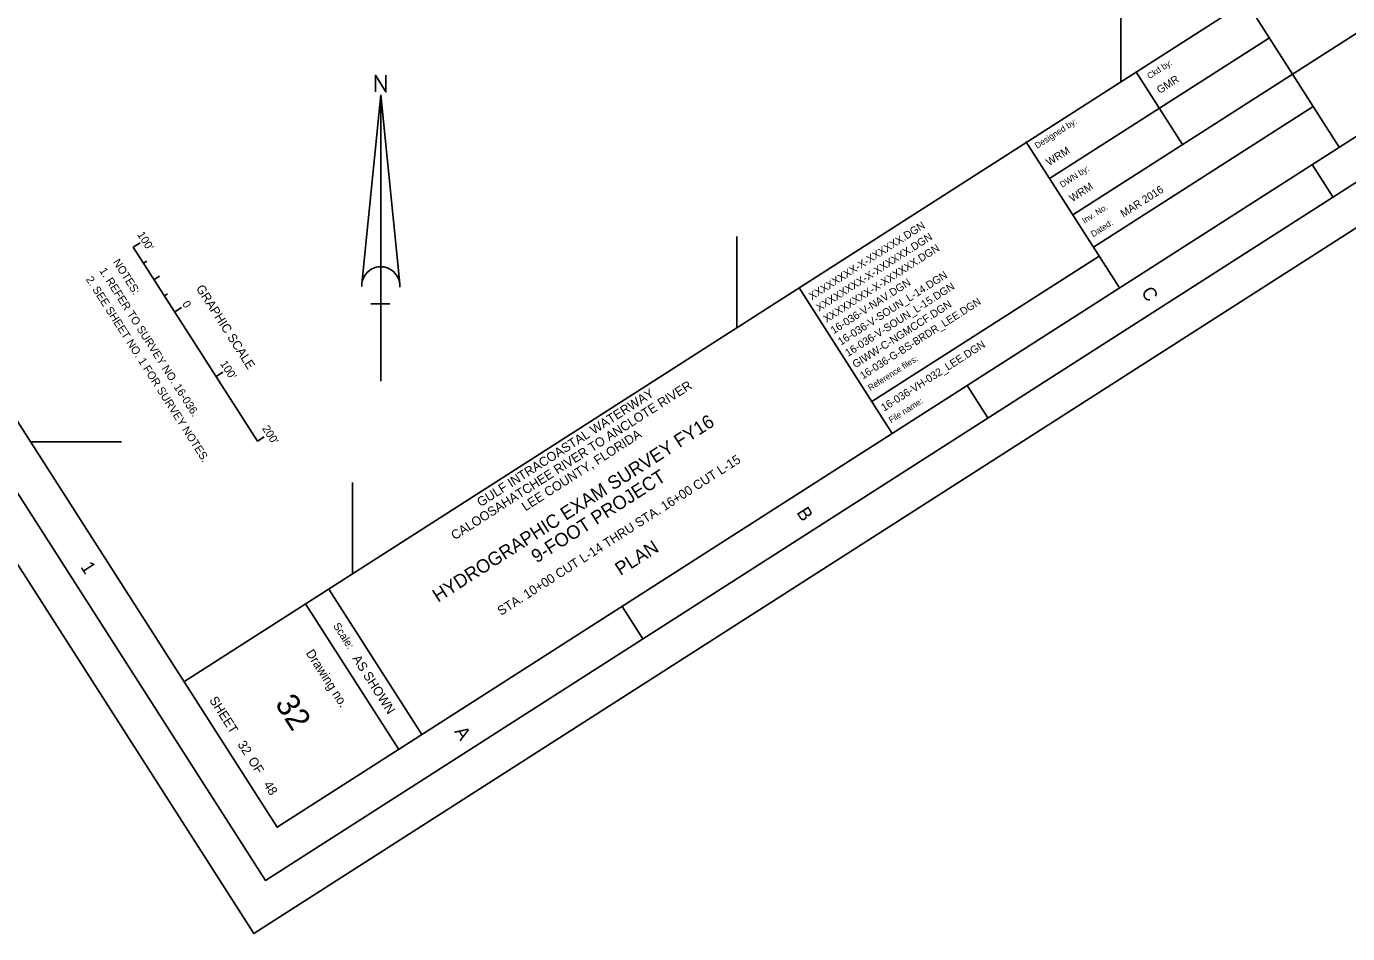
# Model space of a CAD drawing. Extents: x 584499 to 589735, y 833860 to 839399.
# Drawn here: x 586575 to 588295, y 833860 to 835040 of the extents above; entities that cross this region are included whole.
import ezdxf

# ---------------------------------------------------------------- set-up
doc = ezdxf.new("R2010")
doc.units = 0
for name, color, linetype in [('G-ANNO-NPLT', 7, 'Continuous'), ('G-ANNO-TEXT-DRWG', 7, 'Continuous'), ('G-ANNO-TEXT-PROJ', 7, 'Continuous'), ('G-ANNO-TEXT-TTLB', 7, 'Continuous'), ('G-ANNO-TTLB', 7, 'Continuous'), ('V-ANNO-NOTE', 7, 'Continuous'), ('V-ANNO-SYMB', 7, 'Continuous'), ('V-TOPO-COOR-STAT', 7, 'Continuous')]:
    doc.layers.add(name, color=color, linetype=linetype)

msp = doc.modelspace()

# ---------------------------------------------------------------- linework, layer by layer
at = {"layer": 'G-ANNO-NPLT'}
msp.add_lwpolyline([(587362.9, 839398.7), (589735, 835692.9), (586871.4, 833859.9), (584499.3, 837565.7)], close=True, dxfattribs=at)
msp.add_lwpolyline([(586913.6, 833886.8), (586871.5, 833859.8), (586844.5, 833901.9)], dxfattribs=at)
at = {"layer": 'G-ANNO-TTLB'}
for p, q in [((589475.5, 835912.7), (586780.4, 834187.6)), ((587937.4, 834795.4), (588661.7, 835258.2)), ((588162.8, 835073.4), (588284.5, 834883.2)), ((587907.3, 834842.5), (588193.5, 835025.4)), ((588019.7, 834981.8), (588080.5, 834886.8)), ((588250.5, 834936.2), (587964.5, 834753.1)), ((587876.5, 834890.6), (587998.4, 834700.1)), ((588276.1, 834818.5), (588249.2, 834860.6)), ((587971.8, 834741.6), (587675.9, 834552.2)), ((587581.2, 834700.2), (587702.5, 834510.6)), ((587827, 834531), (587800, 834573.1)), ((586968.8, 834308.2), (587090.2, 834118.7)), ((586938.8, 834289), (587060.1, 834099.5)), ((587377.8, 834243.5), (587350.9, 834285.6))]:
    msp.add_line(p, q, dxfattribs=at)
for points in [[(584568.4, 837550.6), (586886.5, 833929), (589665.9, 835708.1), (587347.7, 839329.7)], [(589596.8, 835723.2), (587373, 839197.4), (584677.9, 837472.3), (586901.7, 833998.1)]]:
    msp.add_lwpolyline(points, close=True, dxfattribs=at)
at = {"layer": 'V-ANNO-NOTE'}
for p, q in [((586714.4, 834753.1), (586723.2, 834758.8)), ((586714.4, 834753.1), (586876.2, 834500.5)), ((586727.9, 834732.1), (586731.9, 834734.7)), ((586741.4, 834711), (586748.6, 834715.6)), ((586754.9, 834690), (586758.9, 834692.6)), ((586768.3, 834668.9), (586777.1, 834674.5)), ((586768.3, 834668.9), (586777.1, 834674.5)), ((586768.3, 834668.9), (586772.5, 834671.6)), ((586822.2, 834584.7), (586831, 834590.3)), ((586876.2, 834500.5), (586885, 834506.1))]:
    msp.add_line(p, q, dxfattribs=at)
at = {"layer": 'V-ANNO-SYMB'}
for p, q in [((587011.9, 834705.4), (587036.6, 834951.2)), ((587036.6, 834578.8), (587036.6, 834951.2)), ((587061.3, 834705.4), (587036.6, 834951.2)), ((587048.4, 834679.4), (587023.6, 834679.4))]:
    msp.add_line(p, q, dxfattribs=at)
msp.add_lwpolyline([(587029.8, 834955.1), (587029.8, 834976.9), (587043.3, 834955.1), (587043.3, 834976.9)], dxfattribs=at)
msp.add_arc((587036.6, 834702.9), 24.8, 355.2984, 182.0673, dxfattribs=at)
at = {"layer": 'V-TOPO-COOR-STAT'}
for p, q in [((588000, 834968.3), (588000, 835087)), ((587500, 834648.2), (587500, 834767)), ((586580.4, 834500), (586699.1, 834500)), ((587000, 834328.2), (587000, 834446.9))]:
    msp.add_line(p, q, dxfattribs=at)

# ---------------------------------------------------------------- texts
at = {"layer": 'G-ANNO-TEXT-DRWG'}
for s, height, rotation, p in [('GMR', 10, 32.6232, (588050.8, 834952.4)), ('WRM', 10, 32.6232, (587906.7, 834858.4)), ('WRM', 10, 32.6232, (587936.9, 834811.6)), ('XXXXXXXX-X-XXXXXX.DGN', 10, 32.6232, (587597.9, 834683.9)), ('XXXXXXXX-X-XXXXXX.DGN', 10, 32.6232, (587607.4, 834669.1)), ('XXXXXXXX-X-XXXXXX.DGN', 10, 32.6232, (587616.8, 834654.4)), ('16-036-V-SOUN_L-14.DGN', 10, 32.6232, (587635.7, 834624.9)), ('16-036-V-NAV.DGN', 10, 32.6232, (587626.2, 834639.7)), ('16-036-V-SOUN_L-15.DGN', 10, 32.6232, (587645.1, 834610.2)), ('GIWW-C-NGMCCF.DGN', 10, 32.6232, (587654.5, 834595.4)), ('16-036-VH-032_LEE.DGN', 10, 32.6232, (587691.9, 834539)), ('STA. 10+00 CUT L-14 THRU STA. 16+00 CUT L-15', 12, 32.6232, (587193.2, 834273.2)), ('PLAN', 17.5, 32.6232, (587348.7, 834325.1)), ('32', 30, 302.6232, (586898.1, 834159.1)), (' 32          48', 12, 302.6232, (586847.3, 834109.9))]:
    msp.add_text(s, height=height, rotation=rotation, dxfattribs=at).set_placement(p)
at = {"layer": 'G-ANNO-TEXT-PROJ'}
for s, height, p in [('MAR 2016', 10, (588003.5, 834791.5)), ('16-036-G-BS-BRDR_LEE.DGN', 9.8, (587664.4, 834580.8)), ('CALOOSAHATCHEE RIVER TO ANCLOTE RIVER', 12, (587132.9, 834371.6)), ('GULF INTRACOASTAL WATERWAY', 12, (587166.7, 834414.7)), ('HYDROGRAPHIC EXAM SURVEY FY16', 17.5, (587111.1, 834290.3)), ('LEE COUNTY, FLORIDA', 12, (587224.9, 834409.1)), ('9-FOOT PROJECT', 17.5, (587239.6, 834341.4))]:
    msp.add_text(s, height=height, rotation=32.6232, dxfattribs=at).set_placement(p)
at = {"layer": 'G-ANNO-TEXT-TTLB'}
for s, height, rotation, p in [('Ckd by:', 8, 32.6232, (588037.4, 834971.7)), ('Designed by:', 8, 32.6232, (587891.2, 834881)), ('DWN by:', 8, 32.6232, (587923.7, 834830.3)), ('Inv. No.', 8, 32.6232, (587952.9, 834783.4)), ('Dated:', 8, 32.6232, (587964.1, 834765.9)), ('Reference files:', 8, 32.6232, (587674, 834565.9)), ('File name:', 8, 32.6232, (587701.1, 834523.9)), ('Scale:', 10, 302.6232, (586974.1, 834260.4)), ('Drawing no.', 12, 302.6232, (586938.6, 834224.9)), ('AS SHOWN', 12, 302.6232, (586999.1, 834217.8)), ('SHEET         OF', 12, 302.6232, (586812.8, 834163.8))]:
    msp.add_text(s, height=height, rotation=rotation, dxfattribs=at).set_placement(p)
at = {"layer": 'G-ANNO-TTLB'}
for s, p in [('C', (588025.9, 834694.8)), ('B', (587577.3, 834407.9)), ('1', (586645.1, 834337.1)), ('A', (587131.9, 834122.8))]:
    msp.add_text(s, height=17.5, rotation=302.6232, dxfattribs=at).set_placement(p)
at = {"layer": 'V-ANNO-NOTE'}
for s, height, p in [("100'", 10.42, (586719.1, 834769.5)), ('NOTES:', 10.42, (586687.4, 834733.7)), ('2. SEE SHEET NO. 1 FOR SURVEY NOTES.', 10.416, (586652.3, 834711.3)), ('1. REFER TO SURVEY NO. 16-036.', 10.416, (586669.8, 834722.5)), ('GRAPHIC SCALE', 11.666, (586795.6, 834699.6)), ('0', 10.4, (586777.6, 834679.3)), ("100'", 10.42, (586827, 834601.6)), ("200'", 10.42, (586881.7, 834517.2))]:
    msp.add_text(s, height=height, rotation=302.6232, dxfattribs=at).set_placement(p)

doc.saveas('drawing.dxf')
